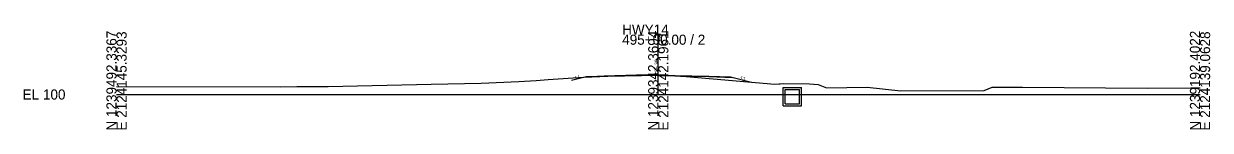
# Model space of a CAD drawing. Extents: x -26 to 303, y -10 to 11521.
# Drawn here: x -25.7 to 302.8, y 6490.3 to 6519.4 of the extents above; entities that cross this region are included whole.
import ezdxf

# ---------------------------------------------------------------- set-up
doc = ezdxf.new("R2010")
doc.units = 0
for name, color, linetype in [('XS_CELL', 7, 'Continuous'), ('XS_P_FINISHED_GRADE', 7, 'Continuous'), ('XS_P_SUBGRADE_GRANULAR', 7, 'Continuous'), ('XS_P_SUBGRADE_LEVELING', 7, 'Continuous'), ('XS_P_TX_FS_BS', 7, 'Continuous'), ('XS_X_DRAINAGE', 7, 'Continuous'), ('XS_X_GROUND', 7, 'Continuous'), ('XS_X_GROUND_TX', 7, 'Continuous')]:
    doc.layers.add(name, color=color, linetype=linetype)

msp = doc.modelspace()

# ---------------------------------------------------------------- linework, layer by layer
at = {"layer": 'XS_CELL'}
for p, q in [((150, 6500), (150, 6516.6)), ((0, 6500), (150, 6500)), ((150, 6500), (300, 6500))]:
    msp.add_line(p, q, dxfattribs=at)
at = {"layer": 'XS_P_FINISHED_GRADE'}
for p, q in [((136, 6505.1), (130, 6504.86)), ((150, 6505.38), (136, 6505.1)), ((150, 6505.38), (164, 6505.1)), ((164, 6505.1), (170, 6504.86)), ((130, 6504.86), (126, 6503.86)), ((170, 6504.86), (175.79, 6503.41))]:
    msp.add_line(p, q, dxfattribs=at)
at = {"layer": 'XS_P_SUBGRADE_GRANULAR'}
for p, q in [((136, 6504.97), (129.4, 6504.71)), ((164, 6504.97), (170.6, 6504.71))]:
    msp.add_line(p, q, dxfattribs=at)
at = {"layer": 'XS_P_SUBGRADE_LEVELING'}
for p, q in [((150, 6505.25), (136, 6504.97)), ((136, 6504.97), (136, 6505.1)), ((150, 6505.25), (164, 6504.97)), ((164, 6504.97), (164, 6505.1))]:
    msp.add_line(p, q, dxfattribs=at)
at = {"layer": 'XS_X_DRAINAGE'}
for p, q in [((184.57, 6501.93), (189.65, 6501.93)), ((184.57, 6496.85), (184.57, 6501.93)), ((189.65, 6496.85), (189.65, 6501.93)), ((185.11, 6497.39), (185.11, 6501.39)), ((185.11, 6501.39), (189.11, 6501.39)), ((189.11, 6497.39), (189.11, 6501.39)), ((184.57, 6496.85), (189.65, 6496.85)), ((185.11, 6497.39), (189.11, 6497.39))]:
    msp.add_line(p, q, dxfattribs=at)
at = {"layer": 'XS_X_GROUND'}
for p, q in [((126.44, 6504.64), (132.46, 6504.97)), ((132.46, 6504.97), (135.01, 6505.15)), ((135.01, 6505.15), (143.93, 6505.44)), ((143.93, 6505.44), (146.82, 6505.53)), ((146.82, 6505.53), (150, 6505.38)), ((150, 6505.38), (154.63, 6505.15)), ((154.63, 6505.15), (157.77, 6504.99)), ((157.77, 6504.99), (182.28, 6502.84)), ((0, 6502.23), (45.52, 6502.17)), ((45.52, 6502.17), (49.88, 6502.25)), ((49.88, 6502.25), (58.59, 6502.25)), ((58.59, 6502.25), (87.15, 6502.87)), ((87.15, 6502.87), (100.97, 6503.1)), ((100.97, 6503.1), (111.4, 6503.59)), ((111.4, 6503.59), (116.23, 6503.85)), ((116.23, 6503.85), (119.56, 6504.13)), ((119.56, 6504.13), (126.44, 6504.64)), ((182.28, 6502.84), (183.36, 6503)), ((183.36, 6503), (183.74, 6502.97)), ((183.74, 6502.97), (184.65, 6503.01)), ((184.65, 6503.01), (191.84, 6502.99)), ((191.84, 6502.99), (194.27, 6502.73)), ((194.27, 6502.73), (196.56, 6501.84)), ((196.56, 6501.84), (207.8, 6502.07)), ((207.8, 6502.07), (217.12, 6500.98)), ((240.28, 6501.11), (242.44, 6502.01)), ((242.44, 6502.01), (250.84, 6502.04)), ((250.84, 6502.04), (285.35, 6501.75)), ((285.35, 6501.75), (297.45, 6501.81)), ((297.45, 6501.81), (300, 6501.81)), ((217.12, 6500.98), (240.28, 6501.11))]:
    msp.add_line(p, q, dxfattribs=at)

# ---------------------------------------------------------------- texts
at = {"layer": 'XS_CELL'}
for s, p in [('HWY14', (140, 6516.6)), ('495+00.00 / 2', (140, 6513.8)), ('EL 100', (-26, 6498.6))]:
    msp.add_text(s, height=2.8, dxfattribs=at).set_placement(p)
for s, p in [('N 1239492.3367', (0, 6490)), ('E 2124145.3293', (2.8, 6490)), ('N 1239342.3694', (150, 6490)), ('E 2124142.1961', (152.8, 6490)), ('N 1239192.4022', (300, 6490)), ('E 2124139.0628', (302.8, 6490))]:
    msp.add_text(s, height=2.8, rotation=90, dxfattribs=at).set_placement(p)
at = {"layer": 'XS_P_TX_FS_BS'}
for rotation, p in [(14.0362, (126.88, 6504.25)), (345.9638, (172.62, 6504.41))]:
    msp.add_text('4:1', height=0.8, rotation=rotation, dxfattribs=at).set_placement(p)
at = {"layer": 'XS_X_GROUND_TX'}
msp.add_text('105.38', height=1, rotation=90, dxfattribs=at).set_placement((150, 6505.48))

doc.saveas('drawing.dxf')
